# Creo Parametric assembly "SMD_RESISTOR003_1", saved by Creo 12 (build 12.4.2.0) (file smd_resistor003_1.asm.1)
Units: Custom; MM, KILOGRAM, SECS

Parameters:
  PTC_WM_ITERATION = "0"
  PTC_WM_VERSION = "-.0"
  PTC_WM_LIFECYCLE_STATE = "In Work"
  PTC_WM_LIFECYCLE = "MO_CADDocument"
  PTC_WM_CREATED_BY = "Maximilian Roepper (Z0017RMS: MO)"
  PTC_WM_CREATED_ON = "18-Sep-26 11:36:42 AM"
  PTC_WM_MODIFIED_BY = "Maximilian Roepper (Z0017RMS: MO)"
  PTC_WM_MODIFIED_ON = "18-Sep-26 11:36:46 AM"
  PDMLINKNUMBER = "PDM000071454787"
  PTC_WM_NUMBER = "PDM000071454787"

Other parameters: WEIGHT, WEIGHT_FACTOR, WEIGHT_ADD, MC_ERRORS, SUPPLIER

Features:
  1. coordinate system
  2. imported feature
  3. component "BODY004_1"
  4. component "CONTACT018_1"
  5. component "CONTACT019_1"
  6. component "LABEL002_1"
  7. component "PART015_1"

Other named items: DRW_VIEW_ORG, ROUGH-GROB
